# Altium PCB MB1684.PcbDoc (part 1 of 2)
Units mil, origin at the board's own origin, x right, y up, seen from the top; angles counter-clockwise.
Board outline 3937.01 x 905.51 mil, 2 copper layers (Top Layer, Bottom Layer), stack 61.811 mil thick; 71 components, 77 nets, 327 pads, 286 vias.
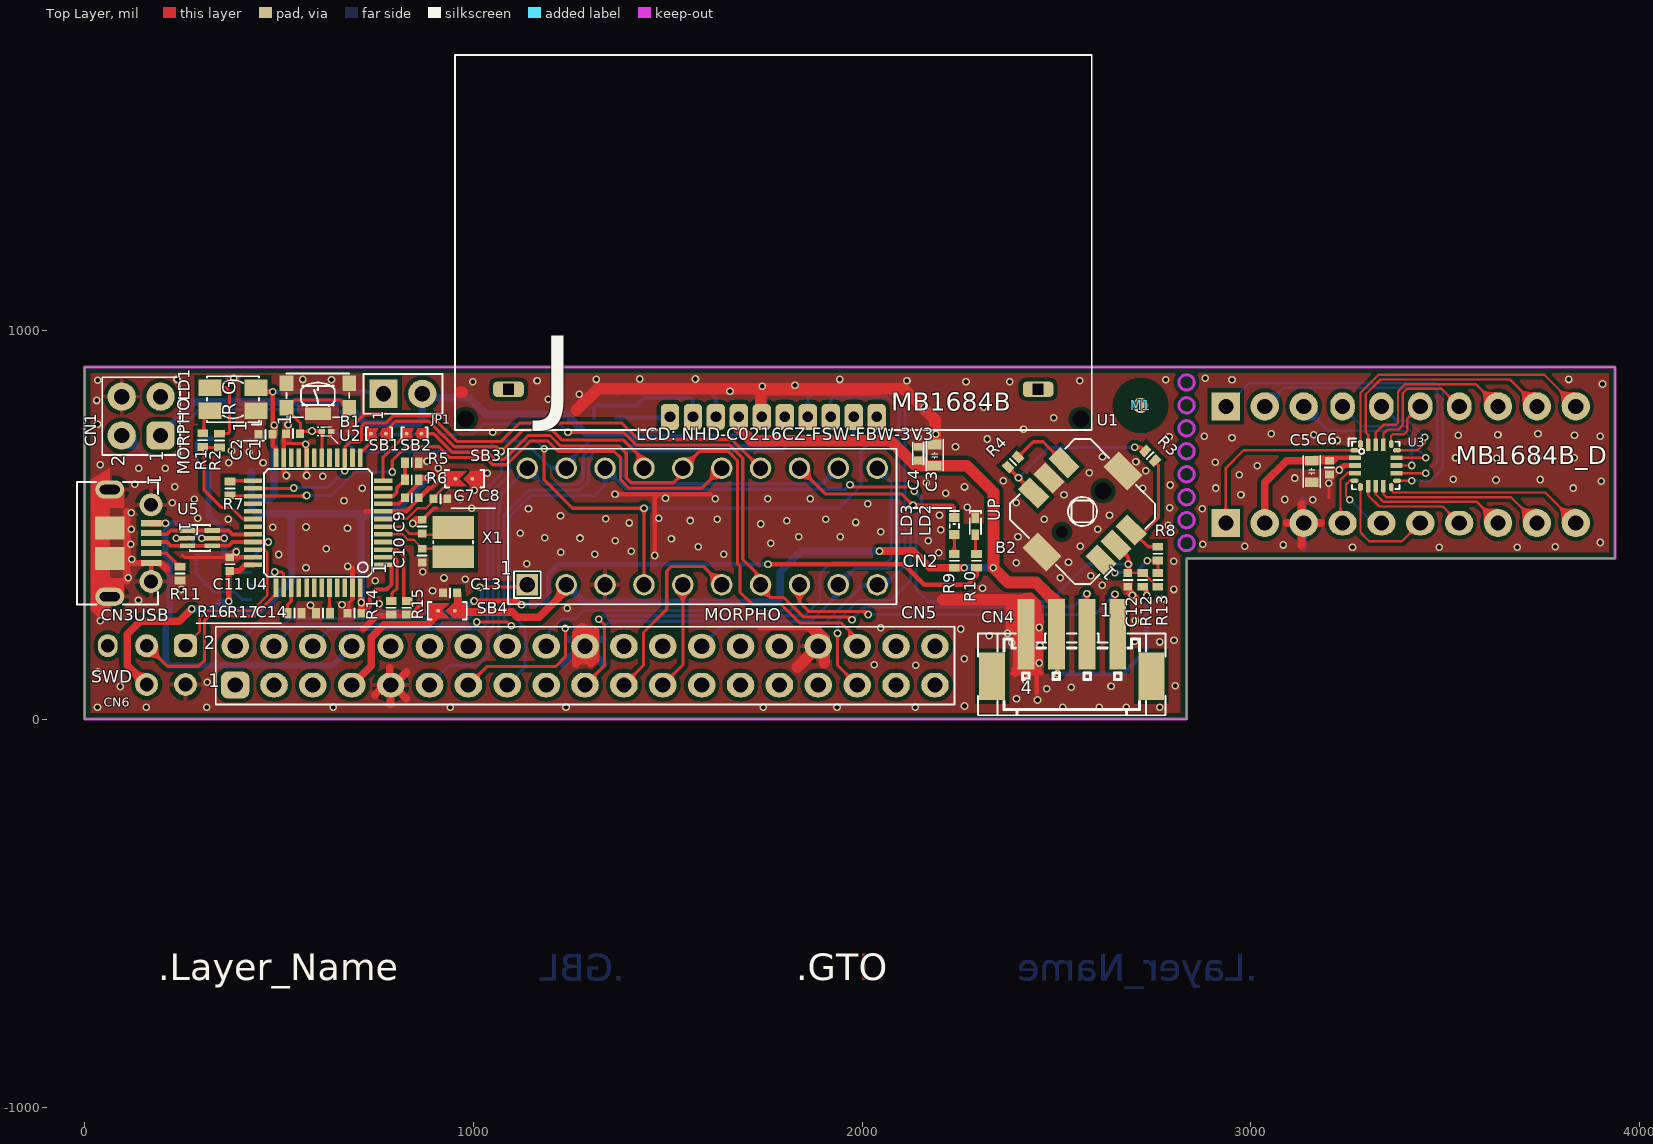
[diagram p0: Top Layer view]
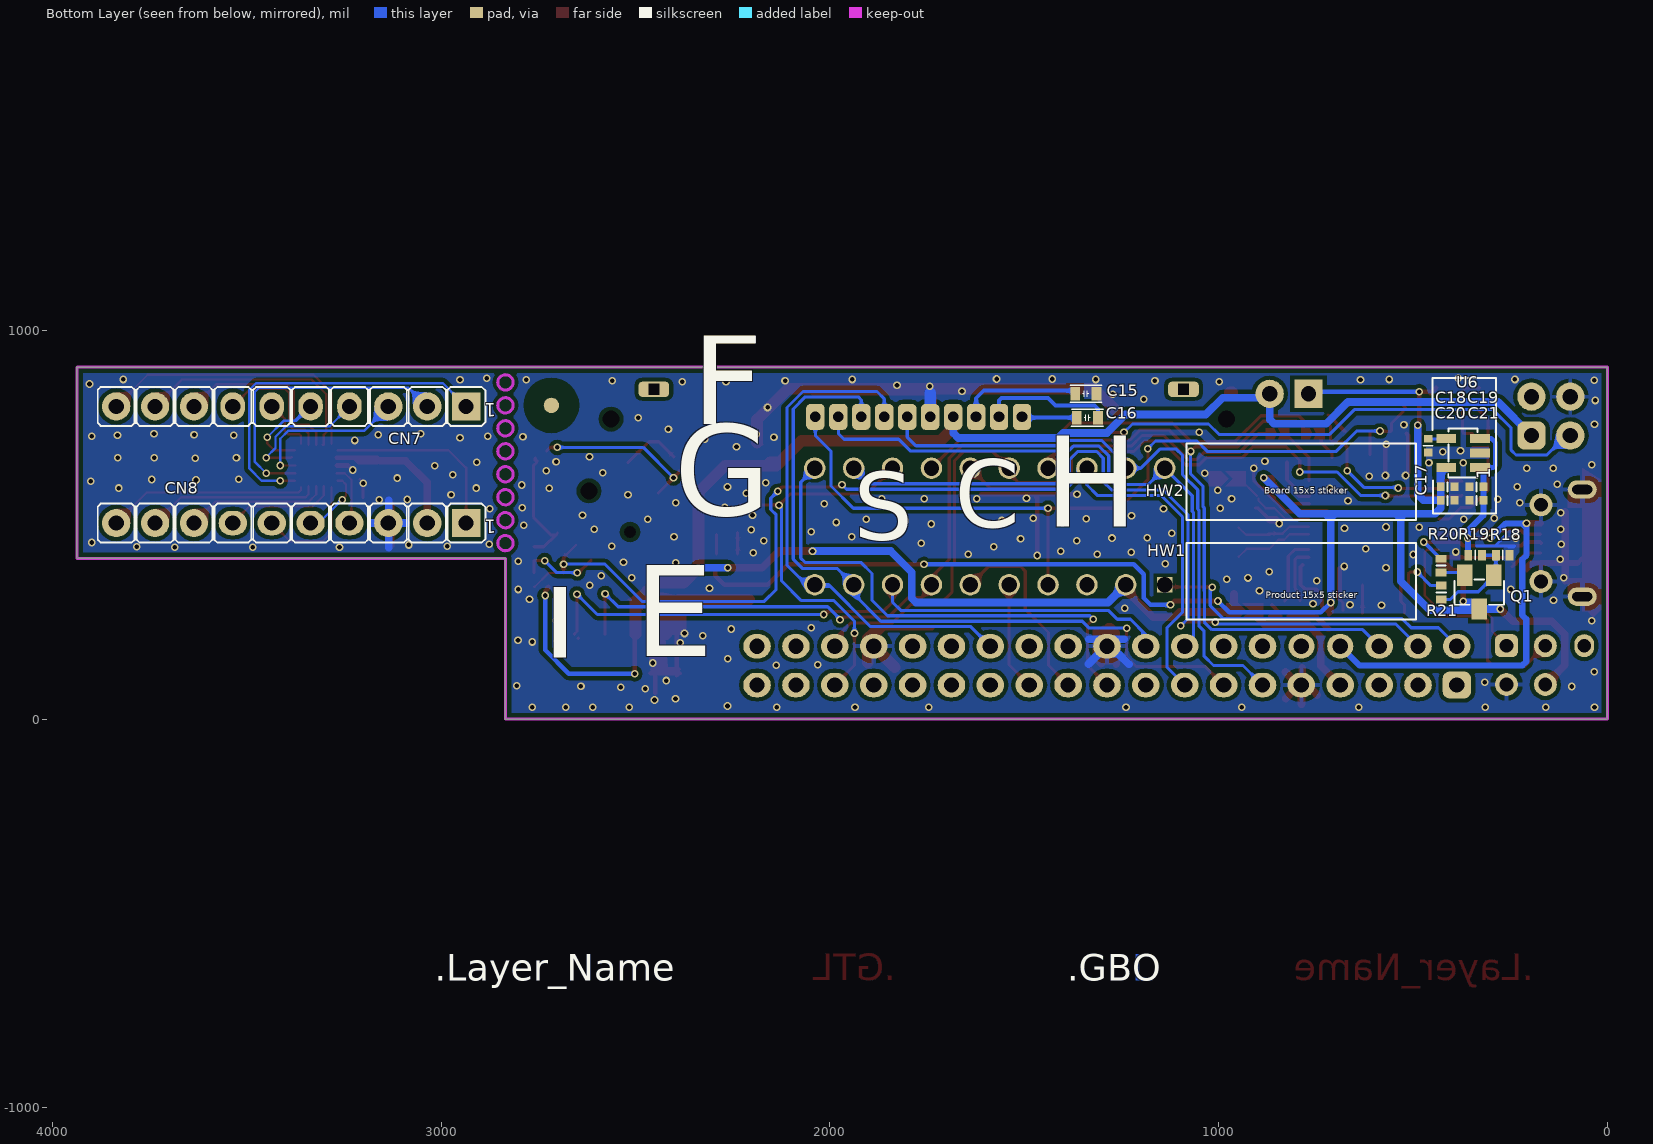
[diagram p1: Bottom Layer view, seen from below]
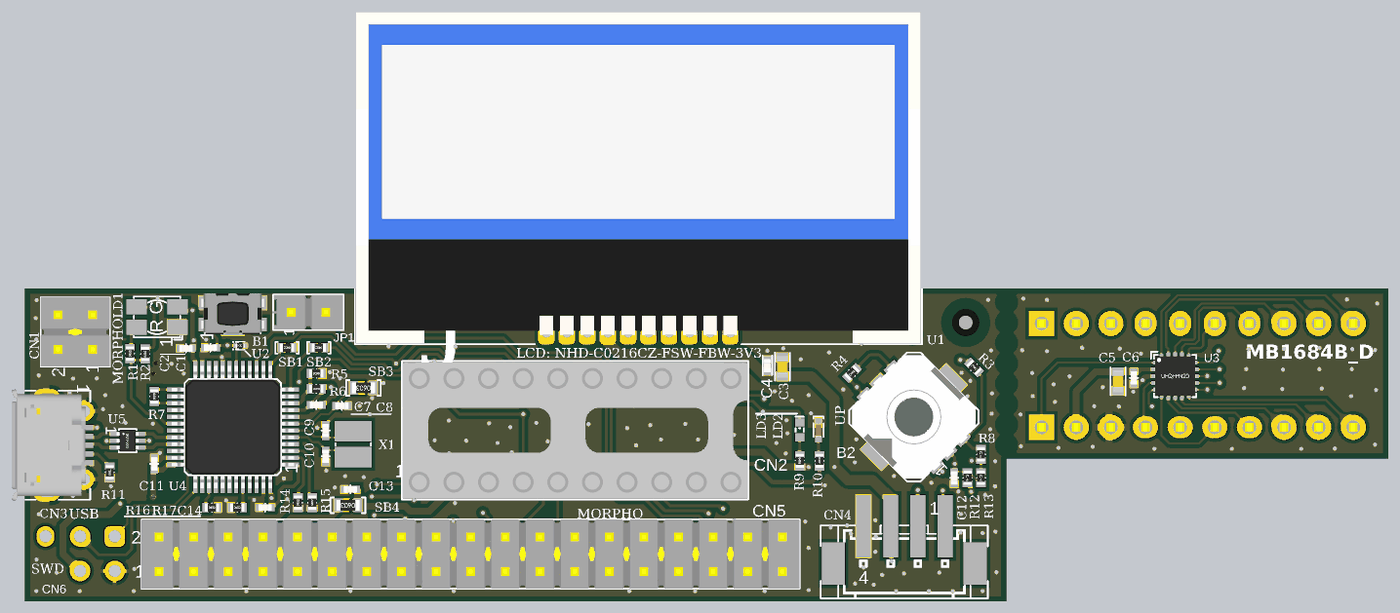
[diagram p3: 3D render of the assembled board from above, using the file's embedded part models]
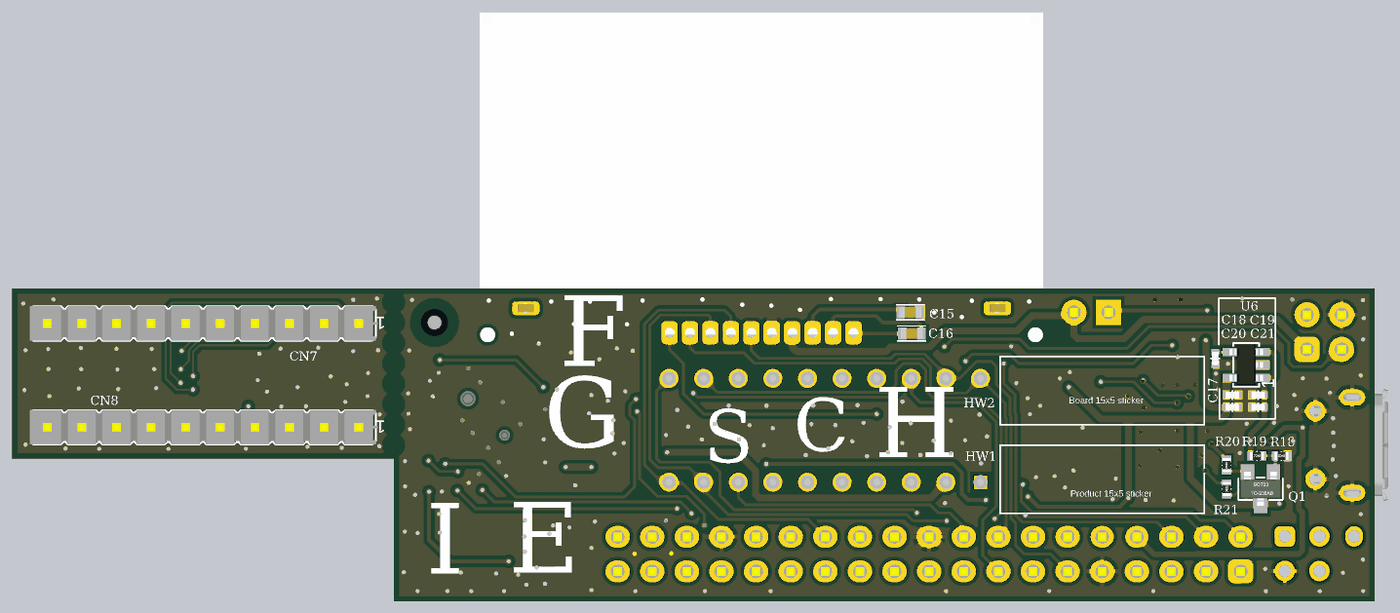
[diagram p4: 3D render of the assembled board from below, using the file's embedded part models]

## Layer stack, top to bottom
Top Solder: solder mask 0.5909, Solder Resist, Dk 3.4
Top Layer: signal copper 1.378
Dielectric 1: core 59.0551, FR-4, Dk 4.6
Bottom Layer: signal copper 1.378
Bottom Solder: solder mask 0.5909, Solder Resist, Dk 3.4

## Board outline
0,0 2834.65,0 2834.65,413.39 3937.01,413.39 3937.01,905.51 2834.65,905.51 0,905.51

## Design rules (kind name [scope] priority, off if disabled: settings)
BoardOutlineClearance [OnLayer('Top Layer') or OnLayer('Bottom Layer') or OnLayer('Inner 1') or OnLayer('Inner 2')] p1: gap=15.75 ignorepadtopadclearanceinfootprint=FALSE
Clearance Clearance_DIFF [InAnyDifferentialPair] p1: gap=4 ignorepadtopadclearanceinfootprint=FALSE except(7: Arc-Fill Arc-Poly Arc-Region Track-Fill Track-Poly Track-Region SMDPad-Fill SMDPad-Poly SMDPad-Region THPad-Fill THPad-Poly THPad-Region Via-Fill Via-Poly Via-Region Fill-Fill Fill-Poly Fill-Region Poly-Poly Poly-Region Region-Region)
Clearance Clearance_via [IsVia vs IsVia] p2: gap=15.75 ignorepadtopadclearanceinfootprint=FALSE
Clearance [All] p3: gap=6 ignorepadtopadclearanceinfootprint=FALSE except(10: Arc-Fill Arc-Poly Arc-Region Track-Fill Track-Poly Track-Region SMDPad-Fill SMDPad-Poly SMDPad-Region THPad-Fill THPad-Poly THPad-Region Via-Fill Via-Poly Via-Region)
ComponentClearance [All] p1: gap=0 collisioncheckmode=3 verticalgap=0 showdistances=FALSE
DiffPairsRouting [All] p1: maxlimit=8 minlimit=8 mostfreqgap=8 toplayer_minwidth=10 toplayer_maxwidth=10 toplayer_prefwidth=10 bottomlayer_minwidth=10 bottomlayer_maxwidth=10 bottomlayer_prefwidth=10 maxuncoupledlength=984.25
HoleSize [All] p1: absolutevalues=TRUE maxlimit=393.7 minlimit=1 maxpercent=80.000 minpercent=20.000
MinimumSolderMaskSliver [All] p1: minsoldermaskwidth=0
PlaneConnect [All] p1: planeconnectstyle=Relief reliefexpansion=20 reliefentries=4 reliefconductorwidth=8.27 reliefairgap=8.27
PolygonConnect PolygonConnect_1 [InComponent('CN1')or InComponent('CN8')] p1: connectstyle=Relief reliefconductorwidth=10 reliefentries=4 polygonreliefangle="90 Angle" airgapwidth=10
PolygonConnect [All] p2: thpad.connectstyle=Relief thpad.reliefconductorwidth=11.81 thpad.reliefentries=4 thpad.polygonreliefangle="90 Angle" thpad.airgapwidth=11.81 smdpad.connectstyle=Direct smdpad.reliefconductorwidth=10 smdpad.reliefentries=4 smdpad.polygonreliefangle="90 Angle" smdpad.airgapwidth=10 via.connectstyle=Direct via.reliefconductorwidth=10 via.reliefentries=4 via.polygonreliefangle="45 Angle" via.airgapwidth=10
RoutingVias [All] p1: holewidth=11.81 width=31.5 viastyle="Through Hole" minholewidth=7.87 minwidth=15.75 maxholewidth=11.81 maxwidth=59.06
SilkToSilkClearance [All] p1: silktosilkclearance=0
SilkToSolderMaskClearance [IsPad] p1: minsilkscreentomaskgap=0 clearancetoexposedcopper=TRUE
SolderMaskExpansion [All] p1: expansion=4 istentingtop=FALSE
Width [All] p1: maxlimit=39.37 minlimit=5 preferedwidth=7.87 minimp=50.000000 maximp=50.000000 favimp=50.000000
23 further rules are at their usual default settings.

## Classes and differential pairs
component class U_Mechanical: HW1 HW2 HW3
component class U_STM32_microcontroller: B1 B2 C1 C3 C4 C5 C6 C12 C13 C15 C16 CN1 CN2 CN4 CN5 CN7 CN8 LD2 LD3 R3 R4 R8 R9 R10 R12 R13 SB4 U1 U2 U3
component class U_ST_LINK_V2_1: C2 C7 C8 C9 C10 C11 C14 C17 C18 C19 C20 C21 CN3 CN6 F JP1 LD1 Q1 R1 R2 R5 R6 R7 R11 R14 R15 R16 R17 R18 R19 R20 R21 SB1 SB2 SB3 U4 U5 U6 X1
differential pair STLK_USB_D: +STLK_USB_D_P -STLK_USB_D_N

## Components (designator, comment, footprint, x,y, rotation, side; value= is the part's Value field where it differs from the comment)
B1 "SW-PUSH-CMS_KMR2_BLACK" SWI_C&K_Y78B23110FP__ITT_KMR231GLFS 600.39,832.67 r180 top value=KMR231GLFS
B2 "Joystick MT-008A_M" SWI_XIEJIA_MT-008A_6P 2566.93,534.17 r135 top locked value=MT-008A
C1 "Capacitor" C0402 536.37,734.25 r0 top value=100nF
C2 "Capacitor" C0402 465.51,732.6 r0 top value=100nF
C3 "Capacitor" C0603 2187.4,679.13 r270 top value=1uF
C4 "Capacitor" C0402 2144.1,682.71 r270 top value=100nF
C5 "Capacitor" C0603 3156.34,637.14 r90 top value=2.2uF
C6 "Capacitor" C0402 3202.25,647.04 r90 top value=100nF
C7 "Capacitor" C0402 841.85,569.16 r180 top value=100nF
C8 "Capacitor" C0402 915.5,566.55 r180 top value=100nF
C9 "Capacitor" C0402 868.63,495.15 r270 top value=10pF
C10 "Capacitor" C0402 868.63,420.74 r90 top value=10pF
C11 "Capacitor" C0402 374.13,398.62 r270 top value=100nF
C12 "Capacitor" C0402 2683.48,358.06 r90 top value=10nF
C13 "Capacitor" C0402 940.13,324.73 r0 top value=100nF
C14 "Capacitor" C0402 694.22,272.55 r0 top value=100nF
C15 "Capacitor" C0603 1341.63,836.61 r0 bottom value=1uF
C16 "Capacitor" C0603 1337.7,775.59 r180 bottom value=1uF
C17 "Capacitor" C0402 461.13,703.26 r90 bottom value=10nF
C18 "Capacitor" C0402 411.42,597.6 r0 bottom value=1uF
C19 "Capacitor" C0402 336.89,597.6 r180 bottom value=100nF
C20 "Capacitor" C0402 411.42,562.6 r0 bottom value=100nF
C21 "Capacitor" C0402 336.89,562.6 r180 bottom value=1uF
CN1 "Header 2x2" CON_SAMTEC_TSW-102-09-G-D 145.67,779.53 r90 top
CN2 "Socket 10x2_DIP20" CON_FCI_DILB20P-223TLF 1588.98,495.65 r180 top locked value=DILB20P-223TLF
CN3 "USB_uB_105017.0001" CON_USBMICROB_MOLEX_105017-0001_H2P90 7.87,452.76 r270 top locked value=USB_uB_105017-0001
CN4 "Header 4x1" CON_988-JIUBABA_A2006LF-04A 2539.37,110.24 r0 top locked
CN5 "Header 19x2" CON_SAMTEC_TSW-119-09-X-D 1287.4,137.8 r0 top locked
CN6 "Header STLINK" HDR_1x5_2R54_V_M 259.84,188.98 r180 top locked
CN7 "Header 10x1" CON_SAMTEC_TSW-110-14-G-S#1 3385.83,804.38 r0 bottom locked
CN8 "Header 10x1" CON_SAMTEC_TSW-110-14-G-S#2 3385.83,504.38 r0 bottom locked
HW1 "STICKER_PRODUCT" STICKER_PRODUCT_15X5 787.4,354.33 r180 bottom locked value="Sticker product"
HW2 "STICKER_BOARD" STICKER_Board_15X5 787.4,610.24 r180 bottom locked value="Sticker board"
JP1 "Jumper_Header 2x1 Fitted" CON_SAMTEC_TSW-102-07-G-S 818.98,836.61 r0 top value="Header 2x1"
LD1 "LD_BICOLOR_CMS" LED_BI-GR_HSMF-A201-A00J1 381.89,822.83 r90 top
LD2 "LED_red" LED_0402_KINGBRIGHT_KPHHS-1005SURCK_HYPER-RED_1A2K_H0P5 2291.54,496.1 r90 top value=RED
LD3 "LED_green" "LED_0402_EVERLIGHT_16-213SYGC/S530-E3-TR8 _YELLOW-GREEN_1A2K_H0P45" 2237.4,496.65 r270 top value="Yellow Green"
M1 "MARK" MARK 2716.54,807.09 r0 top
Q1 "9013-SOT23" NPN_SOT23 329.92,326.6 r0 bottom value="NPN SOT23"
R1 "Resistor" R0402 304.09,717.51 r90 top value=330R
R2 "Resistor" R0402 347.4,716.54 r90 top value=330R
R3 "Resistor" R0402 2740.85,677.67 r135 top value=1K8
R4 "Resistor" R0402 2388.28,661.37 r45 top value=5K1
R5 "Resistor" R0402 841.85,659.71 r180 top value=4K7
R6 "Resistor" R0402 841.85,615.66 r180 top value=4K7
R7 "Resistor" R0402 374.13,593.6 r270 top value=100R
R8 "Resistor" R0402 2760.83,425.6 r90 top value=820R
R9 "Resistor" R0402 2237.4,407.27 r270 top value=680R
R10 "Resistor" R0402 2294.49,407.27 r270 top value=680R
R11 "Resistor" R0402 245.35,374.39 r90 top value=100K
R12 "Resistor" R0402 2721.66,358.06 r90 top value=2K
R13 "Resistor" R0402 2760.83,358.06 r90 top value=510R
R14 "Resistor" R0402 788.7,286.55 r90 top value=10K
R15 "Resistor" R0402 830.04,286.55 r90 top value=10K
R16 "Resistor" R0402 540.31,272.55 r0 top value=4K7
R17 "Resistor" R0402 613.41,272.55 r0 top value=100K
R18 "Resistor" R0402 269.39,421.71 r0 bottom value=36K
R19 "Resistor" R0402 340.25,421.71 r0 bottom value=10K
R20 "Resistor" R0402 428.13,394.94 r270 bottom value=1K5
R21 "Resistor" R0402 427.63,325.83 r90 bottom value=100R
SB1 "SB_ON" SOLDER-BRIDGE_R0402-0R 757.41,734.25 r180 top
SB2 "SB_ON" SOLDER-BRIDGE_R0402-0R 848.98,734.25 r180 top
SB3 "SB_OFF" SOLDER-BRIDGE_R0603-0R 977.78,618.19 r180 top
SB4 "SB_OFF" SOLDER-BRIDGE_R0603-0R 933.07,278.93 r180 top
U1 "NHD-C0216CZ-FSW-FBW-3V3" LCD_NHD_C0216CZ_FSW_FBW_3V3 956.69,748.03 r0 top locked
U2 "ESD-TRANSIL" ESD_ST0201 622.13,740.41 r0 top value=ESDALC6V1-1U2
U3 "STM32C011F6U6" ICC_UFQFPN20_3X3_P050 3321.28,652.42 r0 top
U4 "STM32F103CBT6" ICC_LQFP48_7X7_P050 600.71,504.92 r90 top locked
U5 "USBLC6-2P6" ESD_SOT666 297,465.55 r270 top
U6 "LDK120M33R" REG_SOT23-5L 371.34,684.6 r90 bottom
X1 "XTAL_2_PINS" CRY_NX3225GD_2P 948.24,455.13 r90 top value=8MHz

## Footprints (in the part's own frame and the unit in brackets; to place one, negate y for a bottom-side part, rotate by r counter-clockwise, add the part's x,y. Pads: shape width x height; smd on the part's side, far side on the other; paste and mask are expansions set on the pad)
C0402 [mm]
  rect 0.51x0.56 smd mask+0.05: 1(-0.45,0) 2(0.45,0)
  silkscreen extent 0,-0.3 0,0.3, body extent -0.5,-0.3 0.5,0.3, height 0.4
C0603 [mm]
  rect 0.64x0.89 smd mask+0.05: 1(-0.7,0) 2(0.7,0)
  silkscreen extent -1.05,-0.55 1.02,0.55, body extent -0.9,-0.5 0.9,0.5, height 1.4
CON_988-JIUBABA_A2006LF-04A [mm] "MCD-01741"
  rect 1.7x3.1 smd mask+0.05: 0(-5.2,0) 0(5.2,0)
  rect 1.1x4.6 smd mask+0.05: 1(3,2.75) 2(1,2.75) 3(-1,2.75) 4(-3,2.75)
  silkscreen extent -6.12,-2.55 6.12,2.8, body extent -6.12,-2.55 6.12,4, height 8.35
CON_FCI_DILB20P-223TLF [mm] "MCD-02204"
  rect 1.4x1.4 / inner round 1 / far side rect 1x1 hole 1 mask+0.05: 1(11.43,3.81)
  round 1.4 hole 1 mask+0.05: 2(11.43,-3.81) 3(8.89,3.81) 4(8.89,-3.81) 5(6.35,3.81) 6(6.35,-3.81) 7(3.81,3.81) 8(3.81,-3.81) 9(1.27,3.81) 10(1.27,-3.81) 11(-1.27,3.81) 12(-1.27,-3.81) 13(-3.81,3.81) 14(-3.81,-3.81) 15(-6.35,3.81) 16(-6.35,-3.81) 17(-8.89,3.81) 18(-8.89,-3.81) 19(-11.43,3.81) 20(-11.43,-3.81)
  silkscreen extent -12.7,-5.08 12.7,5.08, body extent -12.7,-5.08 12.7,5.08, height 5.25
CON_SAMTEC_TSW-102-07-G-S [mm]
  rect 1.85x1.85 / inner round 1.85 / far side rect 1.85x1.85 hole 1 mask+0.05: 1(-1.27,0)
  round 1.85 hole 1 mask+0.05: 2(1.27,0)
  silkscreen extent -2.58,-1.3 2.58,1.3, body extent -2.67,-1.3 2.58,1.3, height 8.38
CON_SAMTEC_TSW-102-09-G-D [mm] "MCD-02440"
  rrect50% 1.85x1.85 hole 1 mask+0.05: 1(-1.27,-1.27)
  round 1.85 hole 1 mask+0.05: 2(-1.27,1.27) 3(1.27,-1.27) 4(1.27,1.27)
  silkscreen extent -2.54,-2.54 2.54,2.54, body extent -2.54,-2.55 2.54,2.54, height 8.38
CON_SAMTEC_TSW-110-14-G-S#1 [mm] "MCD-01591"
  rect 1.85x1.85 / inner round 1.85 / far side rect 1.85x1.85 hole 1 mask+0.05: 1(-11.43,0)
  round 1.85 hole 1 mask+0.05: 2(-8.89,0) 3(-6.35,0) 8(6.35,0) 9(8.89,0) 10(11.43,0)
  oval 1.6x1.85 hole 1 mask+0.05: 4(-3.81,0) 5(-1.27,0) 6(1.27,0) 7(3.81,0)
  silkscreen extent -12.7,-1.27 12.64,1.27, body extent -12.7,-1.27 12.64,1.27, height 10.67
CON_SAMTEC_TSW-110-14-G-S#2 [mm] "MCD-01591"
  rect 1.85x1.85 / inner round 1.85 / far side rect 1.85x1.85 hole 1 mask+0.05: 1(-11.43,0)
  round 1.85 hole 1 mask+0.05: 2(-8.89,0) 3(-6.35,0) 8(6.35,0) 9(8.89,0) 10(11.43,0)
  oval 1.85x1.6 hole 1 mask+0.05: 4(-3.81,0) 5(-1.27,0) 6(1.27,0) 7(3.81,0)
  silkscreen extent -12.7,-1.27 12.64,1.27, body extent -12.83,-1.27 12.7,1.27, height 10.67
CON_SAMTEC_TSW-119-09-X-D [mm]
  rrect50% 1.85x1.75 hole 1 mask+0.05: 1(-22.86,-1.27)
  oval 1.8x1.6 hole 1 mask+0.05: 2(-22.86,1.27) 3(-20.32,-1.27) 4(-20.32,1.27) 5(-17.78,-1.27) 6(-17.78,1.27) 7(-15.24,-1.27) 9(-12.7,-1.27) 11(-10.16,-1.27) 12(-10.16,1.27) 13(-7.62,-1.27) 14(-7.62,1.27) 15(-5.08,-1.27) 16(-5.08,1.27) 17(-2.54,-1.27) 18(-2.54,1.27) 19(0,-1.27) 20(0,1.27) 21(2.54,-1.27) 22(2.54,1.27) 23(5.08,-1.27) 24(5.08,1.27) 25(7.62,-1.27) 26(7.62,1.27) 27(10.16,-1.27) 28(10.16,1.27) 29(12.7,-1.27) 30(12.7,1.27) 31(15.24,-1.27) 32(15.24,1.27) 33(17.78,-1.27) 34(17.78,1.27) 35(20.32,-1.27) 36(20.32,1.27) 37(22.86,-1.27) 38(22.86,1.27)
  oval 1.7x1.6 hole 1 mask+0.05: 8(-15.24,1.27) 10(-12.7,1.27)
  silkscreen extent -24.13,-2.54 24.13,2.54, body extent -24.13,-2.55 24.13,2.54, height 8.38
CON_USBMICROB_MOLEX_105017-0001_H2P90 [mm]
  rect 0.4x1.35 smd mask+0.05: 1(-1.3,4.15) 2(-0.65,4.15) 3(0,4.15) 4(0.65,4.15) 5(1.3,4.15)
  round 1.5 hole 0.9 mask+0.05: 6(-2.5,4.15) 7(2.5,4.15)
  oval 1.2x1.9 hole 0.6 slot 1.3 at 90 deg mask+0.05: 8(3.5,1.45) 9(-3.5,1.45)
  rect 1.5x1.9 smd mask+0.05: 10(-1,1.45) 11(1,1.45)
  Top Layer region: 2.3,2.4 3.5,2.4 3.5,0.5 2.3,0.5 2.3,2.4
  Top Layer region: -3.5,2.4 -2.3,2.4 -2.3,0.5 -3.5,0.5 -3.5,2.4
  silkscreen extent -4,-0.7 4,4.6, body extent -4.1,-1.15 4.1,4.66, height 2.9
CRY_NX3225GD_2P [mm]
  rect 1.5x2.7 smd mask+0.05: 1(-0.95,0) 2(0.95,0)
  silkscreen extent -0.1,-1.3 0.1,1.3, body extent -1.65,-1.3 1.65,1.3, height 1
ESD_SOT666 [mm]
  rect 0.3x0.99 smd mask+0.05: 1(-0.5,-0.805) 2(0,-0.805) 3(0.5,-0.805) 4(0.5,0.805) 5(0,0.805) 6(-0.5,0.805)
  silkscreen extent -0.85,-0.65 0.85,0.65, body extent -0.85,-0.8 0.85,0.8, height 0.6
ESD_ST0201 [mm]
  rect 0.425x0.33 smd mask+0.05: 1(-0.312,0) 2(0.312,0)
  silkscreen extent -0.55,-0.3 0.33,0.3, body extent -0.34,-0.18 0.34,0.18, height 0.34
HDR_1x5_2R54_V_M [mm] "Header IDC, 2 x 4 Pin Vertical 2.54mm Pitch (Non-Boxed, Male)"
  rrect50% 1.5x1.5 hole 0.9: 1(0,0)
  round 1.5 hole 0.9: 2(0,2.54) 3(2.54,0) 4(2.54,2.54)
  oval 1.3x1.5 hole 0.9: 5(5.08,0)
ICC_LQFP48_7X7_P050 [mm]
  rect 0.3x1.2 smd mask+0.05: 1(-2.75,-4.25) 2(-2.25,-4.25) 3(-1.75,-4.25) 4(-1.25,-4.25) 5(-0.75,-4.25) 6(-0.25,-4.25) 7(0.25,-4.25) 8(0.75,-4.25) 9(1.25,-4.25) 10(1.75,-4.25) 11(2.25,-4.25) 12(2.75,-4.25) 25(2.75,4.25) 26(2.25,4.25) 27(1.75,4.25) 28(1.25,4.25) 29(0.75,4.25) 30(0.25,4.25) 31(-0.25,4.25) 32(-0.75,4.25) 33(-1.25,4.25) 34(-1.75,4.25) 35(-2.25,4.25) 36(-2.75,4.25)
  rect 1.2x0.3 smd mask+0.05: 13(4.25,-2.75) 14(4.25,-2.25) 15(4.25,-1.75) 16(4.25,-1.25) 17(4.25,-0.75) 18(4.25,-0.25) 19(4.25,0.25) 20(4.25,0.75) 21(4.25,1.25) 22(4.25,1.75) 23(4.25,2.25) 24(4.25,2.75) 37(-4.25,2.75) 38(-4.25,2.25) 39(-4.25,1.75) 40(-4.25,1.25) 41(-4.25,0.75) 42(-4.25,0.25) 43(-4.25,-0.25) 44(-4.25,-0.75) 45(-4.25,-1.25) 46(-4.25,-1.75) 47(-4.25,-2.25) 48(-4.25,-2.75)
  silkscreen extent -3.52,-3.52 3.52,3.52, body extent -4.5,-4.5 4.5,4.5, height 1.6
ICC_UFQFPN20_3X3_P050 [mm] "MCD-02302"
  oct 0.525x0.3 smd mask+0.05: 1(-1.4,1) 5(-1.4,-1) 11(1.4,-1) 15(1.4,1)
  rrect25% 0.8x0.3 smd mask+0.05: 2(-1.35,0.5) 3(-1.35,0) 4(-1.35,-0.5) 12(1.35,-0.5) 13(1.35,0) 14(1.35,0.5)
  oct 0.3x0.525 smd mask+0.05: 6(-1,-1.4) 10(1,-1.4) 16(1,1.4) 20(-1,1.4)
  rrect25% 0.3x0.8 smd mask+0.05: 7(-0.5,-1.35) 8(0,-1.35) 9(0.5,-1.35) 17(0.5,1.35) 18(0,1.35) 19(-0.5,1.35)
  silkscreen extent -1.78,-1.55 1.54,1.78, body extent -1.5,-1.5 1.5,1.5, height 0.55
LCD_NHD_C0216CZ_FSW_FBW_3V3 [mm] "MCD-02205"
  round 0 hole 1.1 unplated: 0(0.6,0.6) 0(40.8,0.6)
  rrect50% 1.2x1.7 hole 0.7 mask+0.05: 1(27.45,0.75) 2(25.95,0.75) 3(24.45,0.75) 4(22.95,0.75) 5(21.45,0.75) 6(19.95,0.75) 7(18.45,0.75) 8(16.95,0.75) 9(15.45,0.75) 10(13.95,0.75)
  rrect50% 2x1 hole 0.7 square mask+0.05: A(3.4,2.55) K(38,2.55)
  silkscreen extent -0.1,-0.1 41.5,24.4, body extent 0,0 41.4,24.3, height 4.1
"LED_0402_EVERLIGHT_16-213SYGC/S530-E3-TR8 _YELLOW-GREEN_1A2K_H0P45" [mm] "MCD-02330"
  rect 0.6x0.7 smd mask+0.05: 1(0.55,0) 2(-0.55,0)
  silkscreen extent -0.98,-0.3 0.12,0.3, body extent -0.55,-0.3 0.55,0.3, height 0.55
LED_0402_KINGBRIGHT_KPHHS-1005SURCK_HYPER-RED_1A2K_H0P5 [mm] "MCD-00708"
  rect 0.7x0.5 smd mask+0.05: 1(-0.55,0) 2(0.55,0)
  silkscreen extent -0.5,-0.38 1,0.38, body extent -0.5,-0.3 0.51,0.3, height 0.6
LED_BI-GR_HSMF-A201-A00J1 [mm] "MCD-00051"
  rect 1.1x1.5 smd mask+0.05: 1(-0.75,-1.5) 2(-0.75,1.5) 3(0.75,1.5) 4(0.75,-1.5)
  silkscreen extent -1.65,-1.85 1.5,1.7, body extent -1.5,-1.85 1.5,1.85, height 2.1
MARK [mm]
  round 1 smd mask+0.05: ""(0,0)
  round 1 smd far side mask+0.05: ""(0,0)
  round 2 on Top Solder mask+0.05: ""(0,0)
  round 2 on Bottom Solder mask+0.05: ""(0,0)
  Top Layer pour cut-out: 1.809,0 1.774,-0.353 1.671,-0.692 1.504,-1.005 1.279,-1.279 1.005,-1.504 0.692,-1.671 0.353,-1.774 0,-1.809 0,-1.809 -0.353,-1.774 -0.692,-1.671 -1.005,-1.504 -1.279,-1.279 -1.504,-1.005 -1.671,-0.692 -1.774,-0.353 -1.809,0 -1.809,0 -1.774,0.353 -1.671,0.692 -1.504,1.005 -1.279,1.279 -1.005,1.504 -0.692,1.671 -0.353,1.774 0,1.809 0,1.809 0.353,1.774 0.692,1.671 1.005,1.504 1.279,1.279 1.504,1.005 1.671,0.692 1.774,0.353 1.809,0
  Bottom Layer pour cut-out: -1.809,0 -1.774,-0.353 -1.671,-0.692 -1.504,-1.005 -1.279,-1.279 -1.005,-1.504 -0.692,-1.671 -0.353,-1.774 0,-1.809 0,-1.809 0.353,-1.774 0.692,-1.671 1.005,-1.504 1.279,-1.279 1.504,-1.005 1.671,-0.692 1.774,-0.353 1.809,0 1.809,0 1.774,0.353 1.671,0.692 1.504,1.005 1.279,1.279 1.005,1.504 0.692,1.671 0.353,1.774 0,1.809 0,1.809 -0.353,1.774 -0.692,1.671 -1.005,1.504 -1.279,1.279 -1.504,1.005 -1.671,0.692 -1.774,0.353 -1.809,0
NPN_SOT23 [mm]
  rect 1x1.4 smd mask+0.05: 1(-0.95,-1.1) 2(0.95,-1.1) 3(0,1.1)
  silkscreen extent -1.63,-0.82 1.63,0.82, body extent -1.56,-1.25 1.56,1.25, height 1.1
R0402 [mm]
  rect 0.51x0.7 smd mask+0.05: 1(-0.45,0) 2(0.45,0)
  silkscreen extent 0,-0.3 0,0.3, body extent -0.52,-0.3 0.52,0.3, height 0.4
REG_SOT23-5L [mm]
  rect 0.6x1.3 smd mask+0.05: 1(-0.95,-1.1) 2(0,-1.1) 3(0.95,-1.1) 4(0.95,1.1) 5(-0.95,1.1)
  silkscreen extent -1.6,-0.95 1.6,0.97, body extent -1.52,-1.25 1.52,1.25, height 1.1
SOLDER-BRIDGE_R0402-0R [mil] "MCD-01619"
  round 10 smd paste-393.7: 1(-17.72,0) 2(20.67,0)
  Top Layer region: 1.48,13.78 8.37,0 1.48,-13.78 30.51,-13.78 30.51,13.78
  Top Layer region: -30.51,-13.78 -30.51,13.78 -8.37,13.78 -1.48,0 -8.37,-13.78
  silkscreen extent -33,-17 33,17, body extent -20,-12 20,12, height 14
SOLDER-BRIDGE_R0603-0R [mil]
  round 10 smd paste-393.7: 1(-19.68,0) 2(23.62,0)
  Top Layer region: -47.24,-19.68 -47.24,19.68 -15.75,19.68 3.94,0 -15.75,-19.68 -47.24,-19.68
  Top Layer region: -5.91,19.68 13.78,0 -5.91,-19.68 47.24,-19.68 47.24,19.68 -5.91,19.68
  silkscreen extent -50,-23 50,23, body extent -36,-20 36,20, height 22
STICKER_Board_15X5 [mil] "Sticker to mention board CPN code"
  silkscreen extent -295,-98 295,98, body extent -295,-98 295,98, height 0
STICKER_PRODUCT_15X5 [mil] "Sticker to mention board CPN code"
  silkscreen extent -295,-98 295,98, body extent -295,-98 295,98, height 0
SWI_C&K_Y78B23110FP__ITT_KMR231GLFS [mm] "MCD-00715"
  rect 0.9x1 smd mask+0.05: 1(2.05,0.8) 2(2.05,-0.8) 3(-2.05,0.8) 4(-2.05,-0.8)
  rect 1.7x0.8 smd mask+0.05: 5(0,1.2)
  silkscreen extent -2.05,-1.43 2.05,1.43, body extent -2.3,-1.5 2.3,1.5, height 2.1
SWI_XIEJIA_MT-008A_6P [mm] "MCD-00132"
  rect 1.8x1.1 smd mask+0.05: 1(-3.1,1.4) 2(-3.1,0) 3(-3.1,-1.4) 4(3.1,1.4) 5(3.1,0) 6(3.1,-1.4)
  rect 2.2x1.4 smd mask+0.05: 7(0,3.75) 8(0,-3.75)
  round 0 hole 0.8 unplated paste-10 mask+0.05: NPTH1(0,1.9)
  round 0 hole 1.1 unplated paste-10 mask+0.05: NPTH2(0,-1.9)
  silkscreen extent -3.7,-3.7 3.7,3.7, body extent -3.85,-3.75 3.85,3.75, height 5.2

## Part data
B1: library part MCD-01485, "Microminiature Tact Switch for SMT - KMR 2 Series - 1.9 mm height", Manufacturer=C&K, Manufacturer_Part_Number=KMR231GLFS
B2: library part MCD-00132, "Joystick, 4 dir, 1 OK", Manufacturer="XIEJIA ELECTRONICS", Manufacturer_Part_Number=MT-008A
C1 C2 C4 C6 C7 C8 C11 C13 C14 C19 C20: library part MCD-00006, "Capacitor, MLCC, 100nF, 16V, X7R, +/-10%, 0402, T=0.5mm", Alternate_Manufacturer=MURATA, Alternate_Manufacturer_Part_Number=GCM155R71C104KA55D, Manufacturer=YAGEO, Manufacturer_Part_Number=CC0402KRX7R7BB104, Package=0402
C3 C15 C16: library part MCD-01100, "Capacitor, MLCC, 1uF, 25V, X5R, +/-10%, 0603, T=0.8mm", Alternate_Manufacturer=MURATA, Alternate_Manufacturer_Part_Number=GCM155R71C104KA55D, Manufacturer=YAGEO, Manufacturer_Part_Number=CC0603KRX5R8BB105, Package=0603
C5: library part MCD-00654, "Capacitor, MLCC, 2.2uF, 16V, X5R, +/-10%, 0603, T=0.8mm", Alternate_Manufacturer=MURATA, Alternate_Manufacturer_Part_Number=GCM155R71C104KA55D, Manufacturer=YAGEO, Manufacturer_Part_Number=CC0603KRX5R7BB225, Package=0603
C9 C10: library part MCD-00015, "Capacitor, MLCC, 10pF, 50V, NPO, +/-5%, 0402, T=0.5mm", Alternate_Manufacturer=MURATA, Alternate_Manufacturer_Part_Number=GCM155R71C104KA55D, Manufacturer=YAGEO, Manufacturer_Part_Number=CC0402JRNPO9BN100, Package=0402
C12 C17: library part MCD-00011, "Capacitor, MLCC, 10nF, 16V, X7R, +/-10%, 0402, T=0.5mm", Alternate_Manufacturer=MURATA, Alternate_Manufacturer_Part_Number=GCM155R71C104KA55D, Manufacturer=YAGEO, Manufacturer_Part_Number=CC0402KRX7R7BB103, Package=0402
C18 C21: library part MCD-00095, "Capacitor, MLCC, 1uF, 25V, X5R, +/-10%, 0402, T=0.5mm", Alternate_Manufacturer=MURATA, Alternate_Manufacturer_Part_Number=GCM155R71C104KA55D, Manufacturer_Part_Number=GRM155R61E105KA12, Package=0402
CN1: library part MCD-02440, "Header, 2x2, 2.54mm, VR, TH, T=5.84mm/10.16mm", Manufacturer=SAMTEC, Manufacturer_Part_Number=TSW-102-09-G-D
CN2: library part MCD-02204, "Socket_IC, 20 (2 x 10) Pos DIP, 0.3\" (7.62mm) Row Spacing Socket Tin Through Hole", Manufacturer="AMPHENOL ICC", Manufacturer_Part_Number=DILB20P-223TLF, Package=DIP20
CN3: library part MCD-00028, "MicroUSB_TypeB, 5pins, 0.65mm, RA, SMD, T=2.9mm", Manufacturer=MOLEX, Manufacturer_Part_Number=1050170001
CN4: library part MCD-01741, "Header, 4x1, 2mm, VR, SMD", Manufacturer=JIUBABA, Manufacturer_Part_Number=A2006LF-04A
CN5: library part MCD-00213, "Header, 19x2, 2.54mm, VR, TH, T=5.84mm/10.16mm", Manufacturer=SAMTEC, Manufacturer_Part_Number=TSW-119-09-G-D
CN6: "Header 5 pads for ST-LINK prog. Not fitted", Manufacturer=n/a
CN7 CN8: library part MCD-02708, "Header, 10x1, 2.54mm, VR, TH, T=5.84mm/2.54mm", Manufacturer=SAMTEC, Manufacturer_Part_Number=TSW-110-07-G-S
HW1: library part MCD-02191, "Sticker product 15x5 mm", Manufacturer=N/A
HW2: library part MCD-02192, "Sticker board 15x5 mm", Manufacturer=N/A
JP1: library part MCD-00683, "Header, 2x1, 2.54mm, VR, TH, T=5.84mm/2.54mm", Alternate_Manufacturer=LIANYI, Alternate_Manufacturer_Part_Number=313102S111116, Manufacturer=SAMTEC, Manufacturer_Part_Number=TSW-102-07-G-S
LD1: library part MCD-02402, "LED Bicolor", Alternate_Manufacturer=EVERLUCK, Alternate_Manufacturer_Part_Number=LE-RGW35280, Manufacturer=EVERLIGHT, Manufacturer_Part_Number=67-22sursygc-s530-a2-tr8
LD2: library part MCD-00708, "LED 0402 Red", Alternate_Manufacturer="OSRAM OPTO SEMICONDUCTORS", Alternate_Manufacturer_Part_Number="LS Q976-NR-1", Manufacturer=KINGBRIGHT, Manufacturer_Part_Number=KPHHS-1005SURCK, Package="LED 0402"
LD3: library part MCD-02330, "LED, Yellow Green, 2V, 25mA, 0402, 0.45mm", Alternate_Manufacturer="OSRAM OPTO SEMICONDUCTORS", Alternate_Manufacturer_Part_Number="LG Q396-PS-35", Manufacturer=EVERLIGHT, Manufacturer_Part_Number=16-213SYGC/S530-E3/TR8, Package=0402
Q1: library part MCD-00073, "NPN Bipolar Transistor", Manufacturer="ON SEMICONDUCTOR", Manufacturer_Part_Number=BSR14, Package=SOT23
R1 R2: library part MCD-00062, "Resistor, 330R, 0402, +/-1%, 1/16W", Alternate_Manufacturer=YAGEO, Alternate_Manufacturer_Part_Number=RT0402FRE07100KL, Manufacturer_Part_Number=RC0402FR-07330RL, Package=0402
R3: library part MCD-00409, "Resistor, 1K8, 0402, +/-1%, 1/16W", Alternate_Manufacturer=YAGEO, Alternate_Manufacturer_Part_Number=RT0402FRE07100KL, Manufacturer_Part_Number=RC0402FR-071K8L, Package=0402
R4: library part MCD-00333, "Resistor, 5K1, 0402, +/-1%, 1/16W", Alternate_Manufacturer=YAGEO, Alternate_Manufacturer_Part_Number=RT0402FRE07100KL, Manufacturer_Part_Number=RC0402FR-075K1L, Package=0402
R5 R6 R16: library part MCD-00065, "Resistor, 4K7, 0402, +/-1%, 1/16W", Alternate_Manufacturer=YAGEO, Alternate_Manufacturer_Part_Number=RT0402FRE07100KL, Manufacturer_Part_Number=RC0402FR-074K7L, Package=0402
R7 R21: library part MCD-00067, "Resistor, 100R, 0402, +/- 1%, 1/16W", Alternate_Manufacturer=YAGEO, Alternate_Manufacturer_Part_Number=RT0402FRE07100KL, Manufacturer_Part_Number=RC0402FR-07100RL, Package=0402
R8: library part MCD-00527, "Resistor, 820R, 0402, +/-1%, 1/16W", Alternate_Manufacturer=YAGEO, Alternate_Manufacturer_Part_Number=RT0402FRE07100KL, Manufacturer_Part_Number=RC0402FR-07820RL, Package=0402
R9 R10: library part MCD-00507, "Resistor, 680R, 0402, +/-1%, 1/16W", Alternate_Manufacturer=YAGEO, Alternate_Manufacturer_Part_Number=RT0402FRE07100KL, Manufacturer_Part_Number=RC0402FR-07680RL, Package=0402
R11 R17: library part MCD-00059, "Resistor, 100K, 0402, +/-1%, 1/16W", Alternate_Manufacturer=YAGEO, Alternate_Manufacturer_Part_Number=RT0402FRE07100KL, Manufacturer_Part_Number=RC0402FR-07100KL, Package=0402
R12: library part MCD-00419, "Resistor, 2K, 0402, +/-1%, 1/16W", Alternate_Manufacturer=YAGEO, Alternate_Manufacturer_Part_Number=RT0402FRE07100KL, Manufacturer_Part_Number=RC0402FR-072KL, Package=0402
R13: library part MCD-00064, "Resistor, 510R, 0402, +/-1%, 1/16W", Alternate_Manufacturer=YAGEO, Alternate_Manufacturer_Part_Number=RT0402FRE07100KL, Manufacturer_Part_Number=RC0402FR-07510RL, Package=0402
R14 R15 R19: library part MCD-00053, "Resistor, 10K, 0402, +/-1%, 1/16W", Alternate_Manufacturer=YAGEO, Alternate_Manufacturer_Part_Number=RT0402FRE07100KL, Manufacturer_Part_Number=RC0402FR-0710KL, Package=0402
R18: library part MCD-00069, "Resistor, 36K, 0402, +/-1%, 1/16W", Alternate_Manufacturer=YAGEO, Alternate_Manufacturer_Part_Number=RT0402FRE07100KL, Manufacturer_Part_Number=RC0402FR-0736KL, Package=0402
R20: library part MCD-00068, "Resistor, 1K5, 0402, +/-1%, 1/16W", Alternate_Manufacturer=YAGEO, Alternate_Manufacturer_Part_Number=RT0402FRE07100KL, Manufacturer_Part_Number=RC0402FR-071K5L, Package=0402
SB1 SB2: library part MCD-01618, "Solder Bridge 0402 ON", Manufacturer=YAGEO, Manufacturer_Part_Number=RC0402JR-070RL, Package=SB0402
SB3 SB4: library part MCD-00072, "Solder Bridge OFF", Manufacturer=YAGEO, Manufacturer_Part_Number=RC0603JR-070RL, Package=SB0603
U1: library part MCD-02205, "Character LCD Display Module Transflective 5 x 8 Dots FSTN - Film Super-Twisted Nematic LED - White Serial", Manufacturer="NEWHAVEN DISPLAY INTL"
U2: library part MCD-00170, "ESD protection 6V1", Manufacturer=STMICROELECTRONICS, Manufacturer_HQ_COO=EU, Manufacturer_Part_Number=ESDALC6V1-1U2
U3: library part MCD-02313, "MCU, ARM™-based 32-bit MCU Cortex-M0+, 32KB Flash, 6KB SRAM", Manufacturer=STMICROELECTRONICS, Package=UFQFPN20
U4: library part MCD-00085, "Medium-density performance line ARM-based 32-bit MCU with 128KB Flash", Manufacturer=STMICROELECTRONICS, Manufacturer_HQ_COO=EU
U5: library part MCD-00169, "USB OTG FS ESD protection", Manufacturer=STMICROELECTRONICS, Manufacturer_HQ_COO=EU
U6: library part MCD-00663, "200 mA low quiescent current very low noise LDO", Manufacturer=STMICROELECTRONICS, Manufacturer_HQ_COO=EU, Package=SOT23-5L
X1: library part MCD-00092, "Crystal, 8MHz, 8pF, +/-20ppm, 500R, 3.2x2.5mm", Manufacturer=NDK, Manufacturer_Part_Number=NX3225GD-8MHZ-EXS00A-CG04874, Package=3.2x2.5mm

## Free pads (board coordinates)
  round 20 on Mech16: 1(648.78,-945.31) 1(2571.9,-945.31)

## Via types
v1: diameter 19.68, hole 11.81, Top Layer to Bottom Layer, tented both sides, 286 vias

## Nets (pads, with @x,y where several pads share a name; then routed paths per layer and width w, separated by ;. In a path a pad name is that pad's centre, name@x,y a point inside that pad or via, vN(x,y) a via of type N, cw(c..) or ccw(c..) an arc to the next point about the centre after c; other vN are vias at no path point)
3V3_STLK: C2.2 C7.2 C11.2 C14.2 C18.2 C20.2 CN6.4 JP1.1 LD1.4 Q1.3 R6.1 R10.2 U4.1 U4.9 U4.24 U4.36 U4.48 U6.5 | length 4869.3
  Top Layer w10: U4.48@708.98,344.75 U4.48@708.98,337.6 708.98,275.96 711.93,273 C14.2@716.42,273 ; U4.48@709.4,314.25 716.4,307.25 C14.2@716.4,281.83 ; C14.2@716.42,268.62 C14.2@716.42,273 ; U4.9@768.03,554.13 809.11,554.13 C7.2@824.13,569.16 824.13,570.34 859.57,605.78 R6.1@859.57,615.66 R6.1@864.57,620.66 ; U4.1@784.09,396.65 789.22,391.53 789.22,345.8 776.96,333.55 748.85,333.55 734.76,319.46 734.76,291.34 C14.2@716.42,273
  Top Layer w11.81: v1(1002,304) 1114,304 v1(1124,294) ; v1(1758,398.28) 2107.11,398.28 2159.73,345.65 2271.65,345.65 2294.49,368.49 R10.2@2294.49,389.55
  Top Layer w12: LD1.4@440.94,852.35 455.3,838 459.3,842 v1(484,842) 484,759.72 v1(488.13,755.6) ; C2.2@486.13,732.6 484.57,731.04 484.57,703.42 491.63,696.36
  Top Layer w15: v1(371.13,303.03) 371.13,377.9 C11.2@374.13,380.9 398,380.9 413.75,396.65 U4.36@433.39,396.65 ; R6.1@864.57,620.66 v1(883.93,620.66)
  Top Layer w19.68: CN6.4@159.84,88.98 110,138.82 110,218.56 143.03,251.59 243.84,251.59 v1(275.65,283.39) ; C2.2@486.13,732.6 488.13,734.6 v1(488.13,755.6)
  Bottom Layer w8: 517.41,525.2 528,514.61 ; 538,513.8 548.59,524.38 ; 698,523 708.59,512.41 ; 716.41,511.41 727,522
  Bottom Layer w11.81: v1(712.22,299.93) 737.6,274.55 972.55,274.55 v1(1002,304) ; v1(1124,294) 1175.4,294 1192.97,311.56 1192.97,372.97 1218.28,398.28 v1(1758,398.28)
  Bottom Layer w12: v1(484,842) 759.55,842 766.96,834.6 JP1.1@768.98,836.61
  Bottom Layer w15: Q1.3@329.92,283.29 349.66,303.03 v1(371.13,303.03) ; Q1.3@347.94,293.2 369.4,293.2 ; Q1.3@348.35,299.8 v1@369.81,299.8 ; 373.4,279.78 v1@373.4,301.25
  Bottom Layer w19.68: v1(275.65,283.39) 329.82,283.39 Q1.3@329.92,283.29 ; Q1.3@329.42,279.71 Q1.3@333.5,279.71 ; Q1.3@331.71,281.5 Q1.3@333.5,279.71 ; C20.2@429.13,562.6 C20.2@432.13,562.6 ; U6.5@429.13,638.07 429.13,602.2 C18.2@429.13,597.6 C20.2@429.13,565.59 ; v1(488.13,755.6) 488.13,577.41 473.31,562.6 C20.2@432.13,562.6 ; v1(712.22,299.93) 712.22,523.55 707.22,528.55 ; v1(883.93,620.66) 791.82,528.55 707.22,528.55 ; Q1.3@333.5,279.71 457.04,279.71 532.13,354.8 532.13,528.55 ; C20.2@429.13,565.59 429.13,543.06 443.65,528.55 532.13,528.55 ; C20.2@429.13,565.59 C20.2@432.13,562.6 ; 532.13,528.55 707.22,528.55
5V_USB_CHGR: C19.2 C21.2 CN3.1 CN5.8 R19.2 U5.5 U6.1 U6.3 | length 1463.8
  Top Layer w12: v1@299.5,465.55 v1(301.33,465.55) U5.5@328.69,465.55 358.95,465.55 v1@359.21,465.29
  Top Layer w15.75: CN3.1@171.65,503.94 v1@208.22,503.94
  Bottom Layer w8: 211.46,489.46 221,499
  Bottom Layer w12: U6.1@328.03,647.19 293.53,647.19 288.39,652.34 288.39,711.6 298.79,722 U6.3@328.03,722
  Bottom Layer w15.75: v1@299.5,465.55 261.5,503.55 v1(208.22,503.55) 208.22,421.78 219.39,410.61 219.39,267.75 209,257.37 209,147.83 218.75,138.09 518.36,138.09 518.65,137.8 637.4,137.8 CN5.8@687.4,187.8 ; U6.1@319.17,643.7 C21.2@319.17,562.6 319.17,524.03 359.21,483.99 v1(359.21,465.55) R19.2@359.21,426.31
AIN_1: R5.2 R6.2 U4.10 | length 124.4
  Top Layer w10: U4.10@768.03,573.82 794.03,573.82 803.09,582.88 803.09,594.62 R6.2@824.13,615.66 R5.2@824.13,659.71
GND: B1.2 B1.4 B1.5 B2.5 B2.7 B2.8 C1.1 C2.1 C3.1 C4.1 C7.1 C8.1 C9.1 C10.1 C11.1 C12.1 C13.1 C14.1 C15.1 C17.1 C18.1 C19.1 C20.1 C21.1 CN1.4 CN2.5 CN3.5 CN3.6 CN3.7 CN3.8 CN3.9 CN3.10 CN3.11 CN4.4 CN5.9 CN5.20 CN5.32 CN6.2 LD1.1 LD2.2 R5.1 R11.1 R14.1 R15.1 R16.2 R17.1 R18.1 SB3.1 U1.6 U2.2 U4.8 U4.20 U4.23 U4.35 U4.47 U5.2 U6.2 | length 5624.3
  Top Layer w6: 830.72,533.76 C7.1@858.62,561.66
  Top Layer w7.87: v1@232,465 v1@232.55,465.55 ; 251.67,421.71 257.04,416.34 C11.1@374.13,416.34 ; 512.13,708.66 v1@564.07,708.66 ; 673.6,739.72 715.13,781.25 ; 677.51,740.73 719.04,782.26 ; C14.1@680.22,278.93 680.22,299.55 689.29,308.62 ; 827.37,534.45 858.77,565.85 858.77,569.16 C7.1@859.57,569.16 ; C7.1@856.57,565.49 C7.1@856.57,569.43 ; C7.1@858.02,569.34 884.38,595.7 ; C7.1@861.42,565.55 861.78,565.55 877.81,581.57 877.81,581.69 910.84,614.72 910.84,647.66 903.95,654.55 ; C9.1@864.91,510.65 867.13,512.86 897.57,543.31 907.23,543.31 ; C9.1@869.12,511.21 899.57,541.66 ; U1.6@1742.13,777.56 1742.13,831.25 1747.49,836.61 2045.4,836.61 ; C3.1@2175.32,706.69 C3.1@2183.46,706.69
  Top Layer w10: 717.16,235.39 737.04,255.26 ; 747.01,264.26 753.25,264.26 R14.1@775.13,264.26 ; R14.1@791.93,264.82 R15.1@820.04,264.82 ; R15.1@840.3,264.93 868.42,264.93 ; R15.1@843.16,273.32 863.04,293.2 ; 1735.4,234.6 1737.5,232.51 1890.69,232.51 CN5.32@1912.4,210.8 ; 1863.4,229.65 CN5.32@1884.93,208.13 ; 1874.4,229.8 CN5.32@1895.93,208.27 ; 1881.4,229.65 CN5.32@1902.93,208.13
  Top Layer w11.81: CN3.11@64.96,413.39 CN3.11@76.77,401.57 ; CN3.7@171.26,354.33 CN3.5@171.26,401.57 189.96,401.57 207.83,383.7 ; CN3.5@197.4,403.26 215.28,385.39 ; C11.1@374.13,416.34 U4.35@433.39,416.34 ; C1.1@516.69,734.25 512.13,729.68 512.13,708.66 U4.23@512.13,672.24 512.13,634.07 v1(519.4,626.8) ; v1(571.18,626.71) U4.20@571.18,672.24 571.18,706.07 v1@571.26,706.15 ; 689.29,308.62 U4.47@689.29,337.6 689.29,388.56 ; 714.26,231.94 720.92,231.94 753.25,264.26 755.64,266.66 804.21,266.66 ; 722.3,534.45 U4.8@768.03,534.45 827.37,534.45 ; v1(1364.57,578.66) 1365.04,578.19 1611.26,578.19 ; v1(1467,421) 1467,569.17 1470.32,572.49
  Top Layer w12: v1@232.55,465.55 U5.2@265.31,465.55 ; 2386.66,117.8 2394.4,117.8 ; 2389.4,128.22 2394.4,128.22 ; 2394.4,112.95 2394.4,117.8 ; 2394.4,216.53 2394.4,128.22 ; 2449.58,67.06 2449.58,117.8 ; v1@2449.58,141.8 2449.58,128.22 ; 2457.4,128.22 2449.58,128.22 ; 2461.4,117.8 2449.58,117.8 ; 2684.17,323.59 2701.4,306.35 ; C12.1@2689.7,330.47 2706.94,313.24 ; 2394.4,117.8 2449.58,117.8 ; 2394.4,117.8 2394.4,128.22 ; 2394.4,128.22 2449.58,128.22 ; 2449.58,117.8 2449.58,128.22
  Top Layer w15.75: CN3.11@76.77,401.57 108.4,401.57 CN3.5@171.26,401.57
  Top Layer w19.68: v1@108.4,355.67 108.4,401.57 108.4,413.39 108.4,533.86
  Top Layer w20: 746.94,62.45 CN5.9@768.98,84.49 ; CN5.9@785.26,100.09 785.26,131.25 ; 787.26,38.25 CN5.9@787.26,69.41 ; CN5.9@805.33,75.29 827.37,53.25 ; CN5.9@806.26,99.1 828.3,121.14 ; v1(844.23,503.19) 853.9,512.86 867.13,512.86 C9.1@868.63,512.86 ; 1263.26,142.09 1263.26,222.25 1278.26,237.25 ; 1275.26,149.97 1306.42,149.97 ; CN5.20@1283.84,205.98 1283.84,237.14 ; CN5.20@1295.26,199.25 1295.26,230.41 ; 1302.38,143.25 1314.16,155.03 1314.16,225.62
  Top Layer w30: 964.98,841.26 971.02,841.26 ; 1265.31,794.26 1321.31,850.26 1427.86,850.26 2107.98,850.26 2187.4,770.84 C3.1@2187.4,710.63 ; U1.6@1739.81,779.97 1739.81,826.02 ; 1833.26,133.66 CN5.32@1887.4,187.8 ; 1902.64,145.6 CN5.32@1902.64,205.94 ; 2208.34,306.9 2389.1,306.9 2421.26,274.74 CN4.4@2421.26,218.5
  Bottom Layer w8: 254.4,442.8 240.91,442.8 238.22,445.49 336.4,445.49 ; 265.48,469.47 288.16,446.8
  Bottom Layer w20: 1231.1,140.99 1258.91,168.8 1308.01,168.8 1335.1,141.71 ; 1243.66,205.71 CN5.20@1278.31,205.71 ; CN5.20@1269.4,196.8 CN5.20@1278.31,205.71 ; CN5.20@1299.32,205.71 CN5.20@1278.31,205.71 ; 1334.07,205.8 1278.4,205.8 CN5.20@1278.31,205.71
  Bottom Layer w30: U1.6@1741.99,792.76 1741.99,838.81
  other v1: 33.4,30.8 158.4,30.8 314.5,30.8 639.76,30.8 940.4,30.8 1238.4,30.8 1745.4,30.8 1935.4,30.8 2136.4,30.8 2515.74,30.8 2610.39,30.8 2679.13,30.8 2765.4,30.8 2263.4,33.8 2451.26,49.25 2397.26,52.25 2475.12,77.93 2538.4,81.8 92,84 2640.4,84.8 2805.4,85.67 316.14,95 2421.26,99.25 34.23,122.02 2138.4,138.8 2031.77,139.8 2455.57,144.37 2263,155.71 2457.57,188.66 2384.84,196.85 2765.4,198.63 2701.4,199.93 2802.4,202.55 2326.77,214.68 2374.02,220.47 2253.4,231.89 2048,234.8 2455.57,235.66 40.4,253.21 2703.1,253.55 1242,285.49 581.22,293.2 662.22,294.26 757.56,296.41 139,306 2772.64,308.77 2695.4,318.87 895.13,330.25 248.77,333.67 2801.4,333.67 2309.81,336.6 2617.44,343.98 748.09,356.12 979,360.24 112.4,363.44 924.63,363.25 2509.81,363.44 2587.9,369.16 870.4,379.19 569.74,389.08 677.4,392.8 1137.4,400.01 2396.63,402.6 2531.06,403.26 2801.65,406.34 121.4,411.38 499.91,423.6 1312.79,424 1644,424 2197,428.4 1225,429 389.87,430.11 1406,432 621.4,437.94 1579,443 2561.4,445.06 118.51,450.29 1765,452.24 2170,458.79 1365.04,459.07 1509.69,463.65 236.4,464.99 1274.4,465.8 1183.46,466.8 1837,469 1944,469 2401.1,469.55 1120.4,477.8 2048,482 2202.1,486.85 119.99,488.8 2606.4,488.11 676.4,490.8 483.81,493.6 569.74,494.31 2787.48,498.77 1739,502 1401.57,504.66 1983.46,506 1806.17,510.43 1558.25,510.82 1627.59,513.8 2468.4,513.8 369.81,514.61 1907,514 1340.58,515.79 291,517.05 1476.86,517 1224.4,523.55 2199.1,524.55 2636.4,524.29 120.51,530.51 1142,541 996.27,542.1 2791.65,543.65 2270.1,544.93 2015.04,554.26 225.81,556.6 2396.4,556.23 667.54,561.66 282,565.49 966.96,566.55 1757.4,566.67 1866.4,566.67 1622.4,567.26 1494.4,568.45 2519.4,577.26 2215.1,580.91 1002.88,588.55 714.64,594.09 2721.52,594.09 232.4,597.34 2263.4,597.3 2792.65,602.23 129.4,603.85 2165.13,608.09 2363,613.51 612.81,624.6 1035.54,632.12 2584.23,634.01 2729.85,638.77 139.54,645.08 207.83,645.65 910.1,645.65 40.4,654.55 371,659.38 459.3,659.45 2704.4,661.93 881.1,663.55 2618.4,674.54 423.81,687.91 378.01,690 2240.4,700.8 569.13,707.1 2322.4,720.67 2144,725.41 2789.65,726.39 2189.81,732.6 1050.37,737.8 2415.4,745.8 523.56,757.46 33.4,758.61 2493.11,774.8 2160.4,801.8 2313.4,802.8 31.65,819.8 1192.97,823 1272.63,836 1660.4,843.8 1743.4,856 1827.4,858.8 998.4,867.8 2267.4,867.8 2379.4,867.8 1164,870.07 2115.4,870.8 2559.75,870.8 34.4,871.8 635.4,872.8 2781.4,872.57 238.1,873.8 561.02,873.8 1316,873.8 1942.4,873.8 1427.86,874.8 1571.4,874.8 383.46,876.55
